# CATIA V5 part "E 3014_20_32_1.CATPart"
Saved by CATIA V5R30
Part number: Tvarova_vlozka_slideru
Definition: E 3014_20_32_1
Nomenclature: E 3014_20_32_1
Source: Unknown
Description: PART--DESC
Bounding box of the stored display mesh (mm): x -9.552 to 56.825, y -16 to 16, z 35 to 52
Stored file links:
  E:\Bakalarka\Model\Forma_v7\E 3014_20_32_1.CATPart
  E:\Bakalarka\Model\Sestava_formy_sliderky\Copy (1) of E 3014_20_32.CATProduct
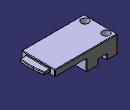
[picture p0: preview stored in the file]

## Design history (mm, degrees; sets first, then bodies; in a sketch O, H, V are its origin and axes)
Body1 "MANIFOLD_SOLID_BREP #135" (main body)
  Solid1: solid without history
  DatumCurve1 to DatumCurve4
  DatumSurface1
  DatumCurve5
  Sketch1 on face of Solid1, origin (0, 16, 0), H (-1, 0, 0), V (0, 0, 1)
    projected line E1 (-10, 30) -> (-10, 0) from edge of DatumCurve1
    projected line E2 (-10, 30) -> (-10, 20) from edge of DatumCurve1
    projected line E3 (-10, 30) -> (-15, 30) from edge of DatumCurve2
    projected line E4 (-15, 30) -> (-185, 30) from edge of DatumCurve3
    projected line E5 (-15, 30) -> (-20, 30) from edge of DatumCurve3
    projected line E6 (-20, 46) -> (-20, 30) from edge of DatumCurve4
    line L1 (-20, 52) -> (5, 52)
    line L2 (5, 52) -> (5, 20)
    line L3 (5, 20) -> (-10, 20)
    point P12 (-10, 20)
    reference projected line E7 (-40, 20) -> (18, 20) from edge [face of Solid1 | face of Solid1]
    line L4 (-20, 52) -> (-58, 52)
    line L5 (-58, 52) -> (-58, 46)
    line L6 (-58, 46) -> (-20, 46)
    point P15 (-20, 46)
    reference intersected line E8 through (0, 46) direction (1, 0) from face of DatumSurface1
    reference projected line E9 (-58, 48.4) -> (-58, 48.1) from edge of DatumCurve5
    distance L3 E7 = 0
    distance L1 L3 = 32
    distance L6 E8 = 0
    distance L5 E9 = 0
    distance L2 E6 = 25
    horizontal: L1 H, L3 H, L4 H, L6 H
    vertical: L2 V, L5 V
    coincidence: P12 E1, P15 E6
  Pad1: profile Sketch1, direction (0, -1, 0), up to face of Solid1
  Sketch2 on face of Solid1, origin (0, -16, 0), H (1, 0, 0), V (0, 0, 1)
    projected line E1 (10, 20) -> (40, 20) from edge [face of Solid1 | face of Solid1]
    projected line E2 (40, 0) -> (0, 0) from edge [face of Solid1 | face of Solid1]
    projected line E3 (40, 0) -> (10, 0) from edge [face of Solid1 | face of Solid1]
    point P3 (40, 0)
    projected line E4 (40, 20) -> (40, 0) from edge [face of Solid1 | face of Solid1]
    point P6 (40, 0)
    line L1 (10, 20) -> (10, 0)
    point P7 (10, 0)
    coincidence: P7 E2, P3 P6
    vertical: L1 V
  Pocket1: profile Sketch2, direction (0, 1, 0), up to face of Solid1
  DatumCurve6 to DatumCurve17
  Sketch3 on face of Pad1 from Sketch1.L5, origin (58, 0, 0), H (0, 1, 0), V (0, 0, 1)
    projected line E1 (-6.6, 50.5) -> (-11.4, 50.5) from edge of DatumCurve7
    projected line E2 (-11.5, 50.4036) -> (-11.5, 48.1) from edge of DatumCurve8
    projected line E3 (-11.4, 48) -> (-6.6, 48) from edge of DatumCurve9
    projected line E4 (-2.4, 48) -> (2.4, 48) from edge of DatumCurve10
    projected line E5 (-2.4, 50.5) -> (2.4, 50.5) from edge of DatumCurve12
    projected line E6 (6.5997, 50.5) -> (11.4, 50.5) from edge of DatumCurve15
    projected line E7 (11.5, 50.4052) -> (11.5, 48.1) from edge of DatumCurve16
    projected line E8 (6.6, 48) -> (11.4, 48) from edge of DatumCurve17
    line L1 (6.5997, 50.5) -> (6.5069, 50.5)
    line L2 (11.5, 50.4052) -> (11.5, 50.5)
    point P18 (11.5, 50.5)
    line L3 (11.4, 50.5) -> (11.5, 50.5)
    line L4 (11.5, 48.1) -> (11.5, 48)
    point P19 (11.5, 48)
    line L5 (11.4, 48) -> (11.5, 48)
    line L6 (6.6, 48) -> (6.5, 48)
    point P21 (2.5, 48)
    line L7 (2.4, 48) -> (2.5, 48)
    line L8 (-2.4, 48) -> (-2.5, 48)
    point P23 (-2.5, 50.5)
    line L9 (-2.4, 50.5) -> (-2.5, 50.5)
    line L10 (2.4, 50.5) -> (2.5078, 50.5)
    line L11 (-11.4, 50.5) -> (-11.5, 50.5)
    point P25 (-11.5, 50.5)
    line L12 (-11.5, 50.4036) -> (-11.5, 50.5)
    line L13 (-11.5, 48.1) -> (-11.5, 48)
    point P26 (-11.5, 48)
    line L14 (-11.4, 48) -> (-11.5, 48)
    line L15 (-6.6, 48) -> (-6.5, 48)
    projected line E9 (16, 52) -> (-16, 52) from edge [face of Pad1 from Sketch1.L4 | face of Pad1 from Sketch1.L5]
    projected line E10 (-16, 52) -> (-16, 46) from edge [face of Solid1 | face of Pad1 from Sketch1.L5]
    projected line E11 (16, 52) -> (16, 46) from edge [face of Pad1 from Sketch1.L5 | face of Solid1]
    projected line E12 (16, 46) -> (-16, 46) from edge [face of Pad1 from Sketch1.L5 | face of Pad1 from Sketch1.L6]
    line L16 (6.5069, 50.5) -> (2.5078, 50.5)
    line L17 (6.5, 48) -> (2.5, 48)
    line L18 (-2.5, 48) -> (-6.5, 48)
    line L19 (-2.5, 50.5) -> (-6.6, 50.5)
    horizontal: L1 H, L3 H, L5 H, L6 H, L7 H, L8 H, L9 H, L10 H, L11 H, L14 H, L15 H, L16 H, L17 H, L18 H, L19 H
    coincidence: P18 E6, P19 E8, P21 E4, P23 E5, P25 E2, P26 E3
    vertical: L2 V, L4 V, L12 V, L13 V
  Pocket2: profile Sketch3, direction (-1, 0, 0), length 8
  DatumCurve18
  DatumCurve19
  DatumSurface2
  DatumCurve20
  DatumSurface3
  DatumCurve21 to DatumCurve34
  DatumSurface4
  DatumCurve35 to DatumCurve44
  DatumSurface5
  DatumCurve45 to DatumCurve47
  DatumSurface6
  Plane1: type Offset, RefPlane DatumSurface6, Offset 0
  DatumCurve48 to DatumCurve60
  Sketch4 on Plane1, origin (0, 0, 48.4), H (1, 0, 0), V (0, 1, 0)
    arc A1 centre (-16.2646, -1.1882) radius 73.0936 from (56.7358, 2.5) to (56.8172, -2.5) cw
    point P9 (56.1948, -11.5)
    line L1 (55.776, 11.1736) -> (55.72, 11.5)
    arc A2 centre (-16.2646, -1.1882) radius 73.0936 from (55.776, 11.1736) to (56.4235, 6.5) cw
    point P13 (56.0979, -11.5)
    point P14 (56.6357, -6.5)
    arc A3 centre (-16.2646, -1.1882) radius 73.0936 from (56.6357, -6.5) to (56.0979, -11.5) cw
    construction line L2 (57.9, -6.5) -> (51, -6.5)
    construction line L3 (57.9, -11.5) -> (51, -11.5)
    construction arc A4 centre (-16.1657, -1.1745) radius 73.0936 from (55.4077, -16.0037) to (56.1948, -11.5) ccw
    point P16 (58, 6.5)
    point P18 (58, 6.5)
    point P22 (58, 11.5)
    point P24 (58, 11.5)
    point P26 (58, 2.5)
    point P28 (58, 2.5)
    point P33 (58, -2.5)
    point P34 (58, -2.5)
    point P36 (58, -6.5)
    point P38 (58, -6.5)
    point P43 (58, -11.5)
    point P44 (58, -11.5)
    construction line L4 (58, 6.5) -> (50, 6.5)
    line L5 (58, 6.5) -> (56.4235, 6.5)
    line L6 (58, 6.5) -> (58, 6.6)
    line L7 (58, 11.4) -> (58, 6.5997)
    line L8 (58, 11.5) -> (58, 11.4)
    construction line L9 (58, 11.5) -> (50, 11.5)
    line L10 (58, 11.5) -> (55.72, 11.5)
    construction line L11 (58, 2.5) -> (50, 2.5)
    line L12 (58, 2.5) -> (56.7358, 2.5)
    line L13 (58, 2.5) -> (58, 2.4)
    line L14 (58, 2.4) -> (58, -2.4)
    line L15 (58, -2.4) -> (58, -2.5)
    construction line L16 (58, -2.5) -> (50, -2.5)
    line L17 (58, -2.5) -> (56.8172, -2.5)
    construction line L18 (58, -6.5) -> (50, -6.5)
    line L19 (58, -6.5) -> (56.6357, -6.5)
    line L20 (58, -6.5) -> (58, -6.6)
    line L21 (58, -6.6) -> (58, -11.4)
    line L22 (58, -11.4) -> (58, -11.5)
    construction line L23 (58, -11.5) -> (50, -11.5)
    line L24 (58, -11.5) -> (56.0979, -11.5)
    radius A1 = 73.0936
    length L1 = 0.3312
    radius A1 = 73.0936 (reference)
    coincidence: P9 A4, L3 P13, A1 A2, L2 P14, A1 A3, P16 P18, P22 P24, P26 P28, P33 P34, P36 P38, P43 P44
    tangency: L1 A1
  Pocket3: profile Sketch4, direction (0, 0, 1), length 8
  Chamfer1: length 0.1, second length 2.1, on edge [face of Pocket3 from Sketch4.A1 | face of Pocket2 from Sketch3.E5]
  Chamfer2: length 0.1, second length 2.1, on edge [face of Pocket3 from Sketch4.A2 | face of Pocket2 from Sketch3.E6]
  Chamfer3: length 0.1, second length 2.1, on edge [face of Pocket3 from Sketch4.A3 | face of Pocket2 from Sketch3.E1]
  Fillet1: radius 0.5, on edge [face of Pad1 from Sketch1.L4 | end face of Pocket2]; edge [face of Solid1 | end face of Pocket2] (x2); edge [face of Pad1 from Sketch1.L6 | end face of Pocket2]; edge [face of Pad1 from Sketch1.L4 | face of Solid1]; face of Pad1 from Sketch1.L4; edge [face of Solid1 | face of Pad1 from Sketch1.L6]; edge [face of Solid1 | face of Pad1 from Sketch1.E6]; edge [face of Pad1 from Sketch1.L6 | face of Solid1]; edge [face of Pad1 from Sketch1.L6 | face of Pad1 from Sketch1.E6]; edge [face of Pad1 from Sketch1.E6 | face of Solid1]; edge [face of Pad1 from Sketch1.E6 | face of Pad1 from Sketch1.E5]; edge [face of Pad1 from Sketch1.E5 | face of Solid1] (x2); edge [face of Pad1 from Sketch1.E3 | face of Pad1]; edge [face of Pad1 | face of Solid1]; edge [face of Solid1 | face of Solid1] (x2); edge [face of Solid1 | face of Pad1] (x2); edge [face of Pad1 from Sketch1.L2 | face of Solid1] (x2)
  Fillet2: radius 0.5, on edge [end face of Pocket2 | face of Pocket2 from Sketch3.E8]
  Body2 "Result of DrillHole"
    Solid2: linked copy from another document
  Assemble1 "DrillHoleCapScrew_E1200_1.1": tool Body2
  Body3 "Result of DrillHole"
    Solid3: linked copy from another document
  Assemble2 "DrillHoleCapScrew_E1200_1.2": tool Body3
  Body4 "Result of DrillHole"
    Solid4: linked copy from another document
  Assemble3 "DrillHoleCapScrew_E1200_2.1": tool Body4
  Body5 "Result of DrillHole"
    Solid5: linked copy from another document
  Assemble4 "DrillHoleCapScrew_E1200_2.2": tool Body5
  Fillet3: radius 0.5, on edge [face of Solid1 | face of Solid1] (x2)
  DatumCurve61 to DatumCurve64
  Sketch5 on face of Pocket2 from Sketch3.L17, origin (0, 0, 48), H (1, 0, 0), V (0, -1, 0)
    projected arc E1 centre (-16.1657, 1.6745) radius 72.9938 from (56.816, 3) to (56.6335, 7) ccw from edge of DatumCurve61
    projected arc E2 centre (-16.1657, 1.6745) radius 72.9938 from (56.094, 12) to (55.31, 16.4835) ccw from edge of DatumCurve62
    projected arc E3 centre (-16.1657, 1.6745) radius 72.9938 from (56.4235, -6) to (56.7355, -2) ccw from edge of DatumCurve63
    point P6 (56.7355, -2)
    projected arc E4 centre (-16.1657, 1.6745) radius 72.9938 from (55.47, -12.3406) to (55.7193, -11) ccw from edge of DatumCurve64
    projected arc E5 centre (-16.1657, 1.6745) radius 72.9938 from (55.6293, -11.5) to (55.7193, -11) ccw from edge of DatumCurve64
    point P8 (55.7193, -11)
    arc A1 centre (-16.1657, 1.6745) radius 72.9938 from (56.6335, 7) to (56.1637, 11.5) ccw
    point P10 (56.094, 12)
    arc A2 centre (-16.1657, 1.6745) radius 72.9938 from (56.816, 3) to (56.7368, -1.9737) cw
    point P12 (56.7368, -1.9737)
    arc A3 centre (-16.1657, 1.6745) radius 72.9938 from (56.4235, -6) to (55.733, -10.9217) cw
    point P14 (55.733, -10.9217)
    projected line E6 (58, -11.5) -> (50.5, -11.5) from edge [face of Pocket2 from Sketch3.L5 | face of Pocket2]
    projected line E7 (58, -11.5) -> (55.6293, -11.5) from edge [face of Pocket2 from Sketch3.L5 | face of Pocket2]
    projected line E8 (58, -6.6) -> (58, -11.4) from edge [face of Pocket2 from Sketch3.E8 | face of Pad1 from Sketch1.L5]
    projected line E9 (58, -2.5) -> (58, -6.5) from edge [face of Pocket2 from Sketch3.L17 | face of Pad1 from Sketch1.L5]
    projected line E10 (58, -2.4) -> (58, -2.5) from edge [face of Pocket2 from Sketch3.L7 | face of Pad1 from Sketch1.L5]
    projected line E11 (58, 2.4) -> (58, -2.4) from edge [face of Pocket2 from Sketch3.E4 | face of Pad1 from Sketch1.L5]
    projected line E12 (58, 6.5) -> (58, 2.5) from edge [face of Pocket2 from Sketch3.L18 | face of Pad1 from Sketch1.L5]
    projected line E13 (58, 11.4) -> (58, 6.6) from edge [face of Pocket2 from Sketch3.E3 | face of Pad1 from Sketch1.L5]
    projected line E14 (58, 6.6) -> (58, 6.5) from edge [face of Pocket2 from Sketch3.L15 | face of Pad1 from Sketch1.L5]
    projected line E15 (58, 11.5) -> (58, 11.4) from edge [face of Pocket2 from Sketch3.L14 | face of Pad1 from Sketch1.L5]
    projected line E16 (58, 11.5) -> (50.5, 11.5) from edge [face of Pocket2 | face of Pocket2 from Sketch3.L14]
    projected line E17 (58, 11.5) -> (56.1637, 11.5) from edge [face of Pocket2 | face of Pocket2 from Sketch3.L14]
    projected line E18 (58, 2.5) -> (58, 2.4) from edge [face of Pocket2 from Sketch3.L8 | face of Pad1 from Sketch1.L5]
    projected line E19 (58, -6.5) -> (58, -6.6) from edge [face of Pocket2 from Sketch3.L6 | face of Pad1 from Sketch1.L5]
    projected line E20 (58, -11.4) -> (58, -11.5) from edge [face of Pocket2 from Sketch3.L5 | face of Pad1 from Sketch1.L5]
    point P41 (56.1637, 11.5)
    point P42 (55.6293, -11.5)
    line L1 (56.7355, -2) -> (56.7368, -1.9737)
    point P43 (56.7355, -2)
    line L2 (55.7193, -11) -> (55.733, -10.9217)
    distance P14 P8 = 0.0795
    length L1 = 0.0263
    radius A1 = 72.9938
    coincidence: A1 P10, P10 E1, A2 P6, P12 E3, A3 P8, P14 E4, E16 P41, E6 P42, P43 E3
    tangency: L1 A2
  Pocket4: profile Sketch5, direction (0, 0, 1), length 8
  DatumCurve65
  DatumCurve66
  Sketch6 on face of Pocket2, origin (0, 11.5, 0), H (-1, 0, 0), V (0, 0, 1)
    projected line E1 (-55.6186, 50.5) -> (-50, 50.5) from edge [face of Pocket2 from Sketch3.L2 | face of Pocket2 from Sketch3.L3]
    projected line E2 (-55.6186, 50.5) -> (-55.4933, 50.5) from edge [face of Pocket2 from Sketch3.L2 | face of Pocket2 from Sketch3.L3]
    projected line E3 (-55.6293, 48) -> (-55.6293, 50.2779) from edge [face of Pocket2 | face of Pocket4 from Sketch5.E5]
    line L1 (-55.6186, 50.5) -> (-55.8186, 50.5)
    line L2 (-55.8186, 50.5) -> (-55.6293, 48.309)
    point P7 (-55.6293, 48.309)
    point P8 (-55.6293, 48.4933)
    reference projected line E4 through (16.1657, 0) direction (0, -1) from axis of face of Pocket4 from Sketch5.A3
    line L3 (-55.4933, 50.5) -> (-55.5656, 48.309)
    line L4 (-55.5656, 48.309) -> (-55.6293, 48.309)
    length L1 = 0.2
    angle E4 L2 = 175.0628
    length L4 = 0.0637
    length L3 = 2.1922
    horizontal: L1 H, L4 H
    coincidence: P7 E3, P8 E3
  DatumSurface7
  DatumCurve67
  Sketch7 on face of Pocket2 from Sketch3.E8, origin (0, 0, 48), H (1, 0, 0), V (0, -1, 0)
    projected arc E1 centre (-16.1657, 1.6745) radius 72.9938 from (55.6476, -11.4) to (55.7193, -11) ccw from edge [face of Pocket2 from Sketch3.E8 | face of Pocket4 from Sketch5.E5]
    projected arc E2 centre (-16.1657, 1.6745) radius 72.9938 from (55.6293, -11.5) to (55.6476, -11.4) ccw from edge [face of Pocket2 from Sketch3.L5 | face of Pocket4 from Sketch5.E5]
    projected arc E3 centre (-16.1657, 1.6745) radius 72.9938 from (55.733, -10.9217) to (56.4235, -6) ccw from edge of DatumCurve67
    projected line E4 (55.733, -10.9217) -> (55.7193, -11) from edge [face of Pocket2 from Sketch3.E8 | face of Pocket4 from Sketch5.L2]
    projected arc E5 centre (-16.1657, 1.6745) radius 72.9938 from (56.4235, -6) to (56.7086, -2.5) ccw from edge [face of Pocket2 from Sketch3.L17 | face of Pocket4 from Sketch5.E3]
    projected arc E6 centre (-16.1657, 1.6745) radius 72.9938 from (56.7086, -2.5) to (56.7142, -2.4) ccw from edge [face of Pocket2 from Sketch3.L7 | face of Pocket4 from Sketch5.E3]
    projected arc E7 centre (-16.1657, 1.6745) radius 72.9938 from (56.7142, -2.4) to (56.7355, -2) ccw from edge [face of Pocket2 from Sketch3.E4 | face of Pocket4 from Sketch5.E3]
    projected line E8 (56.7368, -1.9737) -> (56.7355, -2) from edge [face of Pocket2 from Sketch3.E4 | face of Pocket4 from Sketch5.L1]
    projected arc E9 centre (-16.1657, 1.6745) radius 72.9938 from (56.7368, -1.9737) to (56.8244, 2.4) ccw from edge [face of Pocket2 from Sketch3.E4 | face of Pocket4 from Sketch5.A2]
    projected arc E10 centre (-16.1657, 1.6745) radius 72.9938 from (56.8244, 2.4) to (56.8234, 2.5) ccw from edge [face of Pocket2 from Sketch3.L8 | face of Pocket4 from Sketch5.A2]
    projected arc E11 centre (-16.1657, 1.6745) radius 72.9938 from (56.8234, 2.5) to (56.816, 3) ccw from edge [face of Pocket2 from Sketch3.L18 | face of Pocket4 from Sketch5.A2]
    projected arc E12 centre (-16.1657, 1.6745) radius 72.9938 from (56.816, 3) to (56.6684, 6.5) ccw from edge [face of Pocket2 from Sketch3.L18 | face of Pocket4 from Sketch5.E1]
    projected arc E13 centre (-16.1657, 1.6745) radius 72.9938 from (56.6684, 6.5) to (56.6617, 6.6) ccw from edge [face of Pocket2 from Sketch3.L15 | face of Pocket4 from Sketch5.E1]
    projected arc E14 centre (-16.1657, 1.6745) radius 72.9938 from (56.6617, 6.6) to (56.6335, 7) ccw from edge [face of Pocket2 from Sketch3.E3 | face of Pocket4 from Sketch5.E1]
    projected arc E15 centre (-16.1657, 1.6745) radius 72.9938 from (56.6335, 7) to (56.1772, 11.4) ccw from edge [face of Pocket2 from Sketch3.E3 | face of Pocket4 from Sketch5.A1]
    projected arc E16 centre (-16.1657, 1.6745) radius 72.9938 from (56.1772, 11.4) to (56.1637, 11.5) ccw from edge [face of Pocket2 from Sketch3.L14 | face of Pocket4 from Sketch5.A1]
  Sketch8 on face of Pocket2 from Sketch3.L17, origin (0, 0, 48), H (1, 0, 0), V (0, -1, 0)
    projected arc E1 centre (-16.1657, 1.6745) radius 72.9938 from (55.6293, -11.5) to (55.6476, -11.4) ccw from edge [face of Pocket2 from Sketch3.L5 | face of Pocket4 from Sketch5.E5]
    projected arc E2 centre (-16.1657, 1.6745) radius 72.9938 from (55.6476, -11.4) to (55.7193, -11) ccw from edge [face of Pocket2 from Sketch3.E8 | face of Pocket4 from Sketch5.E5]
    projected arc E3 centre (-16.1657, 1.6745) radius 72.9938 from (55.733, -10.9217) to (56.3575, -6.6) ccw from edge [face of Pocket2 from Sketch3.E8 | face of Pocket4 from Sketch5.A3]
    projected line E4 (55.733, -10.9217) -> (55.7193, -11) from edge [face of Pocket2 from Sketch3.E8 | face of Pocket4 from Sketch5.L2]
    projected arc E5 centre (-16.1657, 1.6745) radius 72.9938 from (56.3575, -6.6) to (56.3689, -6.5) ccw from edge [face of Pocket2 from Sketch3.L6 | face of Pocket4 from Sketch5.A3]
    projected arc E6 centre (-16.1657, 1.6745) radius 72.9938 from (56.3689, -6.5) to (56.4235, -6) ccw from edge [face of Pocket2 from Sketch3.L17 | face of Pocket4 from Sketch5.A3]
    projected arc E7 centre (-16.1657, 1.6745) radius 72.9938 from (56.4235, -6) to (56.7086, -2.5) ccw from edge [face of Pocket2 from Sketch3.L17 | face of Pocket4 from Sketch5.E3]
    projected arc E8 centre (-16.1657, 1.6745) radius 72.9938 from (56.7086, -2.5) to (56.7142, -2.4) ccw from edge [face of Pocket2 from Sketch3.L7 | face of Pocket4 from Sketch5.E3]
    projected arc E9 centre (-16.1657, 1.6745) radius 72.9938 from (56.7142, -2.4) to (56.7355, -2) ccw from edge [face of Pocket2 from Sketch3.E4 | face of Pocket4 from Sketch5.E3]
    projected arc E10 centre (-16.1657, 1.6745) radius 72.9938 from (56.7368, -1.9737) to (56.8244, 2.4) ccw from edge [face of Pocket2 from Sketch3.E4 | face of Pocket4 from Sketch5.A2]
    projected arc E11 centre (-16.1657, 1.6745) radius 72.9938 from (56.8244, 2.4) to (56.8234, 2.5) ccw from edge [face of Pocket2 from Sketch3.L8 | face of Pocket4 from Sketch5.A2]
    projected arc E12 centre (-16.1657, 1.6745) radius 72.9938 from (56.8234, 2.5) to (56.816, 3) ccw from edge [face of Pocket2 from Sketch3.L18 | face of Pocket4 from Sketch5.A2]
    projected arc E13 centre (-16.1657, 1.6745) radius 72.9938 from (56.816, 3) to (56.6684, 6.5) ccw from edge [face of Pocket2 from Sketch3.L18 | face of Pocket4 from Sketch5.E1]
    projected arc E14 centre (-16.1657, 1.6745) radius 72.9938 from (56.6684, 6.5) to (56.6617, 6.6) ccw from edge [face of Pocket2 from Sketch3.L15 | face of Pocket4 from Sketch5.E1]
    projected arc E15 centre (-16.1657, 1.6745) radius 72.9938 from (56.6617, 6.6) to (56.6335, 7) ccw from edge [face of Pocket2 from Sketch3.E3 | face of Pocket4 from Sketch5.E1]
    projected arc E16 centre (-16.1657, 1.6745) radius 72.9938 from (56.6335, 7) to (56.1772, 11.4) ccw from edge [face of Pocket2 from Sketch3.E3 | face of Pocket4 from Sketch5.A1]
    projected arc E17 centre (-16.1657, 1.6745) radius 72.9938 from (56.1772, 11.4) to (56.1637, 11.5) ccw from edge [face of Pocket2 from Sketch3.L14 | face of Pocket4 from Sketch5.A1]
  Sketch9 on face of Pocket2 from Sketch3.E5, origin (0, 0, 50.5), H (1, 0, 0), V (0, 1, 0)
    projected arc E1 centre (-16.1659, -1.6745) radius 72.994 from (56.7355, 2) to (55.6293, 11.5) ccw from Sketch8
    projected arc E2 centre (-16.1657, -1.6745) radius 72.9938 from (56.1637, -11.5) to (56.7368, 1.9737) ccw from Sketch8
    line L1 (56.7368, 1.9737) -> (56.7355, 2)
    tangency: L1 E1
  Rib1: profile Sketch6, centre curve Sketch9
  DatumCurve68
  DatumCurve69
  Sketch10 on face of Rib1, origin (0, 11.5, 0), H (-1, 0, 0), V (0, 0, 1)
    projected line E1 (-55.4997, 50.4052) -> (-55.6293, 48.4933) from edge of DatumCurve68
    projected line E2 (-55.8186, 50.5) -> (-55.6293, 48.309) from edge [face of Rib1 | face of Rib1]
    point P3 (-55.8186, 50.5)
    projected line E3 (-55.8186, 50.5) -> (-50, 50.5) from edge [face of Rib1 | face of Rib1]
    projected line E4 (-55.8186, 50.5) -> (-55.4933, 50.5) from edge [face of Rib1 | face of Rib1]
    point P5 (-55.8186, 50.5)
    projected line E5 (-55.4933, 50.5) -> (-55.4997, 50.4052) from edge of DatumCurve69
    line L1 (-55.6293, 48.4933) -> (-55.6293, 48.309)
    vertical: L1 V
    coincidence: P3 P5
  Slot1: profile Sketch10, centre curve Sketch9
  Fillet4: radius 0.5, on edge [face of Pocket2 from Sketch3.L5 | face of Rib1]
  Fillet5: radius 0.5, on edge [face of Pocket2 | face of Pocket2 from Sketch3.L14]
  DatumSurface8
  Fillet6: radius 0.5, on edge [face of Rib1 | face of Rib1]; face of Rib1
  DatumCurve70
  Sketch11 on face of Solid1, origin (0, -16, 0), H (1, 0, 0), V (0, 0, 1)
    projected line E1 (-8, 9) -> (-8, 14) from edge [face of Solid1 | face of Solid1]
    projected line E2 (-18, 9) -> (-8, 9) from edge [face of Solid1 | face of Solid1]
    projected line E3 (-18, 9) -> (-18, 20) from edge of DatumCurve70
    projected line E4 (-18, 20) -> (-5, 20) from edge [face of Fillet3 | face of Solid1]
    projected line E5 (-5, 20) -> (-5, 51.5) from edge [face of Fillet1 | face of Pad1 from Sketch1.L2]
    projected arc E6 centre (-4.5, 51.5) radius 0.5 from (-4.5, 52) to (-5, 51.5) ccw from edge [face of Fillet1 | face of Fillet1]
    projected line E7 (-4.5, 52) -> (20, 52) from edge [face of Fillet1 | face of Pad1 from Sketch1.L1]
    projected line E8 (20, 45.5) -> (20, 30.5) from edge [face of Fillet1 | face of Pad1 from Sketch1.E6]
    projected arc E9 centre (19.5, 30.5) radius 0.5 from (19.5, 30) to (20, 30.5) ccw from edge [face of Fillet1 | face of Fillet1]
    projected line E10 (19.5, 30) -> (15, 30) from edge [face of Fillet1 | face of Pad1 from Sketch1.E5]
    projected line E11 (15, 30) -> (10.5, 30) from edge [face of Fillet1 | face of Pad1 from Sketch1.E3]
    projected arc E12 centre (10.5, 29.5) radius 0.5 from (10.5, 30) to (10, 29.5) ccw from edge [face of Fillet1 | face of Fillet1]
    projected line E13 (10, 29.5) -> (10, 0.5) from edge [face of Fillet1 | face of Pad1]
    projected arc E14 centre (9.5, 0.5) radius 0.5 from (9.5, 0) to (10, 0.5) ccw from edge [face of Fillet1 | face of Fillet1]
    projected line E15 (9.5, 0) -> (0, 0) from edge [face of Fillet1 | face of Solid1]
    point P30 (0, 0)
    projected line E16 (0, 14) -> (0, 0.5) from edge [face of Solid1 | face of Solid1]
    projected line E17 (-8, 14) -> (0, 14) from edge [face of Solid1 | face of Solid1]
    line L1 (20, 52) -> (20, 45.5)
    line L2 (0, 0.5) -> (0, 0)
    vertical: L1 V, L2 V
    coincidence: O P30
  Pocket5: profile Sketch11, direction (0, 1, 0), through (limit type 6)
  DatumCurve71
  DatumCurve72
  Sketch12 on face of Solid1, origin (0, -16, 0), H (1, 0, 0), V (0, 0, 1)
    line L1 (20, 52) -> (-9.552, 52)
    line L2 (-9.552, 52) -> (-9.552, 35)
    line L3 (-9.552, 35) -> (0.548, 35)
    line L4 (0.548, 35) -> (0.548, 40)
    line L5 (0.548, 40) -> (8.548, 40)
    line L6 (8.548, 40) -> (8.548, 35)
    line L7 (8.548, 35) -> (19.3064, 35)
    line L8 (19.3064, 35) -> (20, 35)
    point P9 (20, 35)
    reference projected line E1 (20, 52) -> (49.5, 52) from edge [face of Fillet1 | face of Pad1 from Sketch1.L4]
    line L9 (20, 35) -> (20, 52)
    reference projected line E2 (20, 46.366) -> (20, 51.5) from edge [face of Solid1 | face of Pocket5 from Sketch11.L1]
    distance L1 E1 = 0
    length L2 = 17
    distance L5 L3 = 5
    length L5 = 8
    distance L7 L3 = 0
    distance P9 E1 = 17
    distance L9 L2 = 29.552
    distance L9 L6 = 11.452
    distance L9 E2 = 0
    horizontal: L1 H, L3 H, L5 H, L7 H
    vertical: L2 V, L4 V, L6 V
  Pad2: profile Sketch12, direction (0, 1, 0), up to face of Solid1
  Chamfer4: length 0.3, angle 45, on edge [face of Pad2 from Sketch12.L5 | face of Pad2 from Sketch12.L6]
  Chamfer5: length 0.3, angle 45, on edge [face of Pad2 from Sketch12.L4 | face of Pad2 from Sketch12.L5]
  Fillet7: radius 0.5, on face of Pad2 from Sketch12.L9
  Fillet8: radius 0.5, on edge [face of Pad2 from Sketch12.L3 | face of Pad2 from Sketch12.L4]
  DatumSurface9 to DatumSurface12
  Sketch13 on face of Pad1, origin (0, 0, 52), H (1, 0, 0), V (0, 1, 0)
    projected circle E1 centre (-4.552, -10) radius 2 from face of DatumSurface11
    projected circle E2 centre (-4.552, 10) radius 2 from face of DatumSurface12
  Pocket6: profile Sketch13, direction (0, 0, -1), through (limit type 6)
  DatumSurface13
  DatumSurface14
  Sketch14 on face of Pad1, origin (0, 0, 52), H (1, 0, 0), V (0, 1, 0)
    projected circle E1 centre (-4.552, -10) radius 3.5 from face of DatumSurface13
    projected circle E2 centre (-4.552, 10) radius 3.5 from face of DatumSurface14
  Pocket7: profile Sketch14, direction (0, 0, -1), length 12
